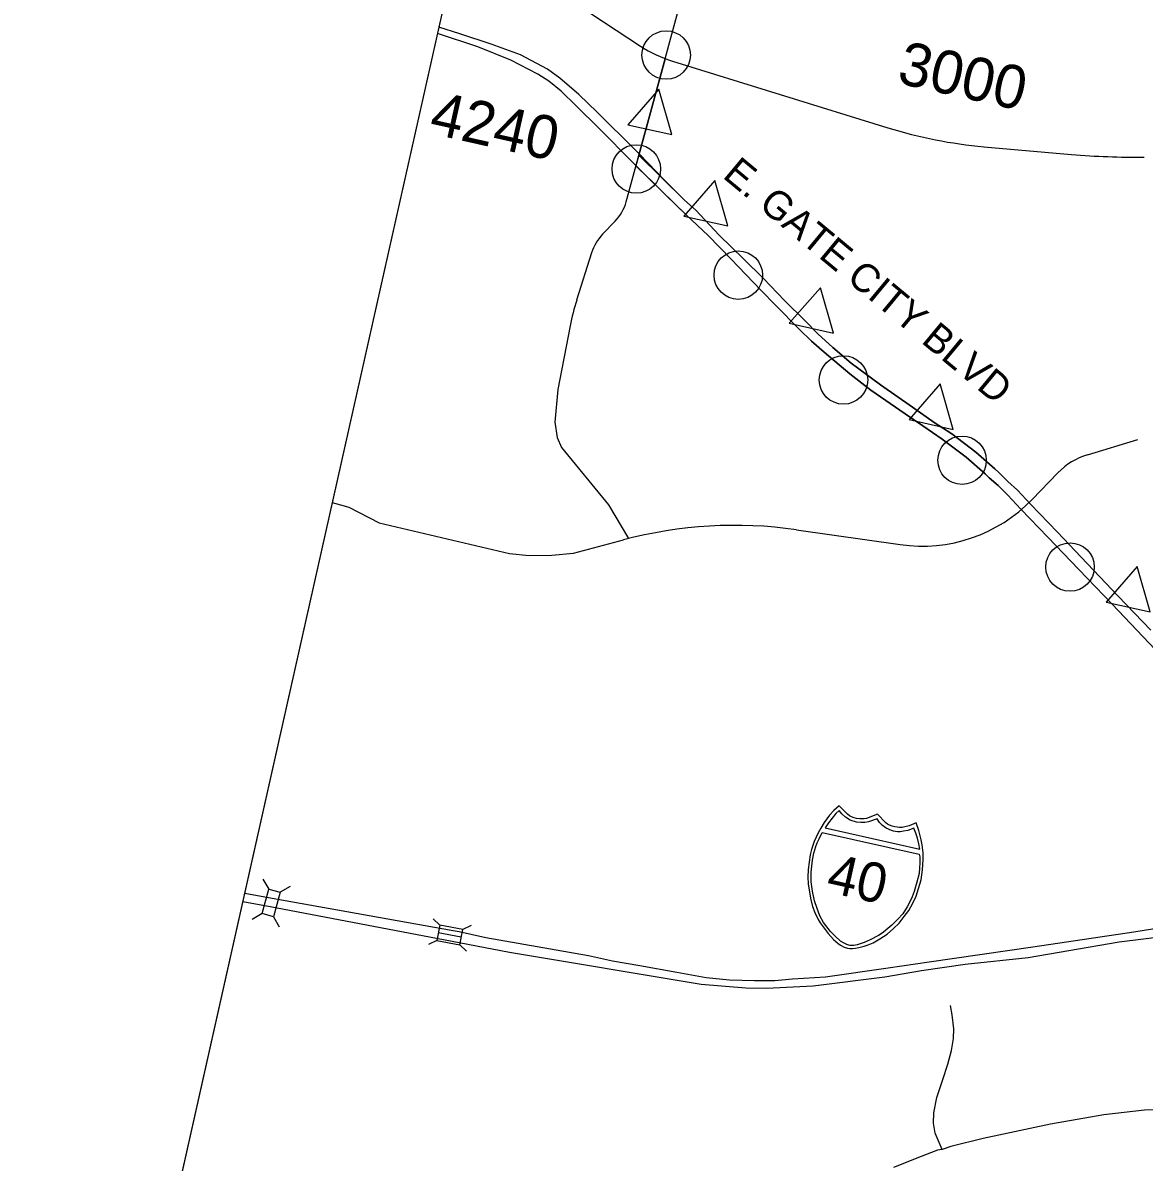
# Model space of a CAD drawing. Extents: x 1784499 to 1786147, y 841097 to 842538.
# Drawn here: x 1784498.9 to 1784672, y 842146.6 to 842322.5 of the extents above; entities that cross this region are included whole.
import ezdxf

# ---------------------------------------------------------------- set-up
doc = ezdxf.new("R2010")
doc.units = 0
for name, color, linetype in [('DEV CONE PLAN VIEW CELL', 7, 'Continuous'), ('Exist Road Non-System Structure Non-Sys NCDOT Attributed CELL', 7, 'Continuous'), ('Exist Road Primary Interstate Divided Center Attributed', 7, 'Continuous'), ('Exist Road Primary Interstate Shield CELL', 7, 'Continuous'), ('Exist Road Primary Interstate Shield Number Label', 7, 'Continuous'), ('Exist Road Primary Interstate Structure Standard Bridge CELL', 7, 'Continuous'), ('Exist Road Secondary Type 51 Attributed', 7, 'Continuous'), ('Exist Road Secondary Type 51 Divided Attributed', 7, 'Continuous'), ('Exist Road Secondary Type 51 Number Label', 7, 'Continuous'), ('Old_Level_1', 7, 'Continuous'), ('Old_Level_40', 7, 'Continuous'), ('Prop DSN Text', 7, 'Continuous'), ('Scratch_Level_3', 7, 'Continuous')]:
    doc.layers.add(name, color=color, linetype=linetype)

msp = doc.modelspace()

# ---------------------------------------------------------------- linework, layer by layer
at = {"layer": 'DEV CONE PLAN VIEW CELL'}
for points in [[(1784597.06, 842312.24), (1784592.26, 842306.76), (1784599.06, 842305.23)], [(1784605.71, 842298.14), (1784600.91, 842292.65), (1784607.71, 842291.13)], [(1784621.99, 842281.6), (1784617.19, 842276.12), (1784623.99, 842274.59)], [(1784640.5, 842266.74), (1784635.7, 842261.26), (1784642.5, 842259.73)], [(1784670.88, 842238.55), (1784666.09, 842233.07), (1784672.89, 842231.54)]]:
    msp.add_lwpolyline(points, close=True, dxfattribs=at)
for centre in [(1784598.19, 842317.51), (1784593.58, 842299.93), (1784609.32, 842283.54), (1784625.55, 842267.36), (1784643.86, 842254.96), (1784660.52, 842238.47)]:
    msp.add_circle(centre, 3.74, dxfattribs=at)
at = {"layer": 'Exist Road Non-System Structure Non-Sys NCDOT Attributed CELL'}
for p, q in [((1784535.95, 842190.3), (1784536.84, 842188.75)), ((1784540.15, 842189.17), (1784538.61, 842188.28)), ((1784535.82, 842184.98), (1784534.31, 842184.08)), ((1784537.58, 842184.5), (1784538.47, 842182.96))]:
    msp.add_line(p, q, dxfattribs=at)
msp.add_lwpolyline([(1784538.61, 842188.28), (1784537.59, 842184.5), (1784535.82, 842184.98), (1784536.84, 842188.75)], close=True, dxfattribs=at)
at = {"layer": 'Exist Road Primary Interstate Divided Center Attributed'}
for p, q in [((1784537.38, 842187.29), (1784533.13, 842188.08)), ((1784565.29, 842182.34), (1784537.38, 842187.29))]:
    msp.add_line(p, q, dxfattribs=at)
for points in [[(1784532.85, 842186.86), (1784537.05, 842186.1), (1784563.83, 842180.98), (1784574.03, 842179.03), (1784603.58, 842174.08), (1784610.49, 842173.51), (1784613.69, 842173.48), (1784620.87, 842173.82), (1784631.94, 842175.24), (1784637.58, 842176.2), (1784644.35, 842177.19), (1784654.07, 842178.21), (1784668.12, 842180.62), (1784691.88, 842183.53)], [(1784695.5, 842186.11), (1784694.75, 842185.99), (1784683.49, 842184.23), (1784670.39, 842182.1), (1784654.76, 842179.82), (1784638.8, 842177.48), (1784632.47, 842176.57), (1784622.77, 842175.18), (1784617.69, 842174.87), (1784614.95, 842174.59), (1784611.84, 842174.62), (1784607.96, 842174.71), (1784604.36, 842175.07), (1784599.81, 842175.9), (1784594.13, 842176.92), (1784589.92, 842177.64), (1784586.2, 842178.48), (1784570.37, 842181.25), (1784566.24, 842182.17), (1784565.29, 842182.34)]]:
    msp.add_lwpolyline(points, dxfattribs=at)
at = {"layer": 'Exist Road Primary Interstate Shield CELL'}
for points in [[(1784626.18, 842179.64), (1784626.51, 842179.59), (1784626.96, 842179.58), (1784627.41, 842179.63), (1784627.94, 842179.73), (1784628.73, 842179.96), (1784629.37, 842180.17), (1784630.13, 842180.46), (1784631.19, 842181.07), (1784632.28, 842181.8), (1784633.3, 842182.67), (1784634.14, 842183.52), (1784634.93, 842184.52), (1784635.62, 842185.46), (1784636.25, 842186.58), (1784636.75, 842187.69), (1784637.14, 842188.87), (1784637.52, 842190.19), (1784637.77, 842191.72), (1784637.86, 842193.32), (1784637.83, 842194.34), (1784637.71, 842195.57), (1784637.57, 842196.37), (1784637.16, 842197.83), (1784636.75, 842198.98), (1784635.68, 842198.53), (1784635, 842198.35), (1784634.6, 842198.27), (1784634.21, 842198.28), (1784633.49, 842198.35), (1784633.06, 842198.47), (1784632.68, 842198.65), (1784632.35, 842198.8), (1784632.1, 842199), (1784630.82, 842200.31), (1784629.1, 842199.67), (1784628.76, 842199.6), (1784628.42, 842199.6), (1784628.09, 842199.59), (1784627.57, 842199.68), (1784627.18, 842199.78), (1784626.8, 842199.94), (1784626.49, 842200.08), (1784626.18, 842200.33), (1784624.87, 842201.64), (1784624.07, 842200.91), (1784623.39, 842200.15), (1784622.59, 842199.05), (1784622.06, 842198.18), (1784621.65, 842197.46), (1784621.05, 842196.1), (1784620.63, 842194.9), (1784620.41, 842194.03), (1784620.08, 842191.81), (1784620.06, 842190.59), (1784620.09, 842189.59), (1784620.44, 842187.38), (1784620.79, 842186.1), (1784621.13, 842185.17), (1784621.66, 842184.08), (1784621.95, 842183.56), (1784623.17, 842181.89), (1784624.03, 842180.97), (1784624.74, 842180.35), (1784625.09, 842180.12), (1784625.65, 842179.82)], [(1784624.89, 842200.9), (1784624.39, 842200.41), (1784623.79, 842199.73), (1784623.26, 842199.01), (1784622.71, 842198.2), (1784637.33, 842194.92), (1784637.16, 842195.75), (1784636.97, 842196.6), (1784636.74, 842197.38), (1784636.43, 842198.16), (1784635.49, 842197.82), (1784634.83, 842197.68), (1784634.32, 842197.62), (1784633.89, 842197.62), (1784633.25, 842197.71), (1784632.97, 842197.79), (1784632.14, 842198.18), (1784631.6, 842198.56), (1784631.11, 842199.06), (1784630.75, 842199.6), (1784629.44, 842199.16), (1784628.87, 842199.05), (1784628.25, 842199.03), (1784627.58, 842199.09), (1784626.61, 842199.42), (1784625.89, 842199.87), (1784625.3, 842200.37)], [(1784637.25, 842194.17), (1784637.32, 842193.73), (1784637.33, 842192.76), (1784637.28, 842192.03), (1784637.22, 842191.19), (1784636.86, 842189.81), (1784636.47, 842188.38), (1784636.15, 842187.56), (1784635.8, 842186.82), (1784635.36, 842186.01), (1784634.71, 842184.95), (1784633.96, 842184.1), (1784633.04, 842183.18), (1784632.1, 842182.4), (1784631.7, 842182.07), (1784630.96, 842181.58), (1784629.67, 842180.95), (1784628.74, 842180.53), (1784627.66, 842180.18), (1784627.13, 842180.07), (1784626.54, 842180.08), (1784626.08, 842180.22), (1784625.55, 842180.49), (1784625.12, 842180.72), (1784624.25, 842181.48), (1784623.56, 842182.2), (1784622.46, 842183.61), (1784621.92, 842184.62), (1784621.47, 842185.77), (1784621.09, 842186.93), (1784620.75, 842188.42), (1784620.59, 842189.87), (1784620.59, 842191.4), (1784620.76, 842193.24), (1784620.98, 842194.33), (1784621.28, 842195.36), (1784621.51, 842195.88), (1784621.79, 842196.53), (1784622.29, 842197.52)]]:
    msp.add_lwpolyline(points, close=True, dxfattribs=at)
at = {"layer": 'Exist Road Primary Interstate Structure Standard Bridge CELL'}
for p, q in [((1784563.23, 842183.17), (1784562.23, 842184.19)), ((1784566.56, 842181.36), (1784563.02, 842182.01)), ((1784568.07, 842183.16), (1784566.78, 842182.54)), ((1784562.8, 842180.83), (1784561.51, 842180.22)), ((1784567.35, 842179.16), (1784566.35, 842180.18))]:
    msp.add_line(p, q, dxfattribs=at)
msp.add_lwpolyline([(1784566.78, 842182.54), (1784563.23, 842183.19), (1784562.8, 842180.83), (1784566.35, 842180.18)], close=True, dxfattribs=at)
at = {"layer": 'Exist Road Secondary Type 51 Attributed'}
for p, q in [((1784592.03, 842294.86), (1784608.26, 842354.55)), ((1784578, 842329.58), (1784594.23, 842318.89)), ((1784599.17, 842316.55), (1784632.42, 842306.26)), ((1784647.24, 842303.36), (1784660.75, 842302.18)), ((1784588.38, 842289.84), (1784590.34, 842291.88)), ((1784586.68, 842286.97), (1784584.36, 842279.69)), ((1784583.35, 842275.72), (1784581.46, 842265.86)), ((1784663.23, 842255.82), (1784671.01, 842258.18)), ((1784582.02, 842256.91), (1784589.29, 842248.07)), ((1784658.65, 842253.02), (1784654.68, 842248.92)), ((1784589.29, 842248.07), (1784592.39, 842242.87)), ((1784618.29, 842244.23), (1784634.32, 842241.94))]:
    msp.add_line(p, q, dxfattribs=at)
for points in [[(1784581.46, 842265.86), (1784580.99, 842260.85), (1784581.37, 842258.45), (1784582.02, 842256.91)], [(1784546.66, 842248.43), (1784549.22, 842247.74), (1784553.87, 842245.32), (1784574, 842240.59), (1784577.05, 842240.26), (1784580.56, 842240.29), (1784583.86, 842240.6), (1784591.58, 842242.66)], [(1784640.81, 842148.57), (1784639.7, 842151.07), (1784639.44, 842152.63), (1784639.52, 842154.21), (1784639.96, 842156.59), (1784640.91, 842159.38), (1784641.68, 842161.75), (1784642.24, 842163.83), (1784642.56, 842165.68), (1784642.61, 842167.17), (1784642.35, 842169.34), (1784642.06, 842170.81)], [(1784753.8, 842155.56), (1784748.67, 842155.57), (1784744.03, 842155.43), (1784738.44, 842155.11), (1784734.44, 842154.67), (1784727.95, 842153.66), (1784725.9, 842153.43), (1784724.28, 842153.35), (1784715.91, 842153.37), (1784708.01, 842153.5), (1784692.53, 842154.16), (1784687.21, 842154.42), (1784680.28, 842154.71), (1784672.03, 842154.64), (1784665.73, 842153.9), (1784657.5, 842152.49), (1784647.14, 842150.27), (1784642.12, 842149.02), (1784640.81, 842148.57)], [(1784640.81, 842148.57), (1784640.05, 842148.48), (1784637.52, 842147.48), (1784633.29, 842145.81)]]:
    msp.add_lwpolyline(points, dxfattribs=at)
for centre, radius, start, end in [((1784604.92, 842335.12), 19.43, 236.6238, 252.8016), ((1784653.41, 842374.08), 70.98, 252.8016, 265.0175), ((1784670.55, 842414.49), 112.74, 265.0175, 270.724), ((1784585.34, 842296.67), 6.92, 316.2178, 344.7891), ((1784593.7, 842284.74), 7.37, 136.2178, 162.3534), ((1784617.45, 842269.17), 34.71, 162.3534, 169.1279), ((1784666.33, 842245.59), 10.69, 106.8881, 135.9796), ((1784637.67, 842265.36), 23.66, 261.8429, 315.9796), ((1784608.8, 842178.01), 66.9, 81.8429, 104.9143)]:
    msp.add_arc(centre, radius, start, end, dxfattribs=at)
at = {"layer": 'Exist Road Secondary Type 51 Divided Attributed'}
for points in [[(1784674.65, 842224.7), (1784667, 842232.72), (1784661.9, 842238.12), (1784657.08, 842243.09), (1784652.92, 842247.39), (1784650.9, 842249.57), (1784649.42, 842251.06), (1784648.04, 842252.27), (1784647.41, 842252.86), (1784644.51, 842255.44), (1784640.78, 842258.23), (1784637.79, 842260.26), (1784635.06, 842262.12), (1784629.79, 842265.8), (1784626.54, 842268.32), (1784622.59, 842271.67), (1784620.63, 842273.34), (1784618.74, 842275.2), (1784615.1, 842278.87), (1784612.78, 842281.23), (1784608.24, 842285.99), (1784604.65, 842289.68), (1784601.3, 842292.8), (1784598.13, 842295.9), (1784592.97, 842300.99), (1784587.91, 842306.14), (1784584.31, 842309.69), (1784581.99, 842311.93), (1784580.08, 842313.49), (1784578.4, 842314.56), (1784574.19, 842316.73), (1784569.12, 842318.78), (1784562.9, 842320.83)], [(1784673, 842228.71), (1784667.96, 842233.99), (1784662.23, 842239.98), (1784658.57, 842243.87), (1784654.43, 842248.16), (1784652.39, 842250.35), (1784650.9, 842251.7), (1784649.53, 842253.06), (1784648.9, 842253.65), (1784646, 842256.23), (1784642.27, 842259.02), (1784639.55, 842260.81), (1784636.21, 842263.14), (1784631.28, 842266.58), (1784626.74, 842269.96), (1784623.92, 842272.38), (1784621.62, 842274.47), (1784619.63, 842276.49), (1784616.46, 842279.6), (1784613.2, 842283.01), (1784610.12, 842286.04), (1784606.39, 842289.73), (1784602.79, 842293.58), (1784601.02, 842295.11), (1784598.02, 842298.07), (1784593.4, 842302.9), (1784587.53, 842308.7), (1784584.7, 842311.43), (1784581.76, 842313.96), (1784579.89, 842315.34), (1784575.68, 842317.52), (1784571.2, 842319.17), (1784566.32, 842320.79), (1784563.12, 842321.83)]]:
    msp.add_lwpolyline(points, dxfattribs=at)
at = {"layer": 'Old_Level_1'}
msp.add_lwpolyline([(1784673, 842228.71), (1784667.96, 842233.99), (1784662.23, 842239.98), (1784658.57, 842243.87), (1784654.43, 842248.16), (1784652.39, 842250.35), (1784650.9, 842251.7), (1784649.53, 842253.06), (1784648.9, 842253.65), (1784646, 842256.23), (1784642.27, 842259.02), (1784639.55, 842260.81), (1784636.21, 842263.14), (1784631.28, 842266.58), (1784626.74, 842269.96), (1784623.92, 842272.38), (1784621.62, 842274.47), (1784619.63, 842276.49), (1784616.46, 842279.6), (1784613.2, 842283.01), (1784610.12, 842286.04), (1784606.39, 842289.73), (1784602.79, 842293.58), (1784601.02, 842295.11), (1784593.98, 842302.04), (1784598.03, 842316.95), (1784593.98, 842302.04), (1784593.53, 842300.39), (1784601.3, 842292.8), (1784604.65, 842289.68), (1784608.24, 842285.99), (1784612.78, 842281.23), (1784615.1, 842278.87), (1784618.74, 842275.2), (1784620.63, 842273.34), (1784622.59, 842271.67), (1784626.54, 842268.32), (1784629.79, 842265.8), (1784635.06, 842262.12), (1784637.79, 842260.26), (1784640.78, 842258.23), (1784644.51, 842255.44), (1784647.41, 842252.86), (1784648.04, 842252.27), (1784649.42, 842251.06), (1784650.9, 842249.57), (1784652.92, 842247.39), (1784657.08, 842243.09), (1784661.9, 842238.12), (1784667, 842232.72), (1784674.65, 842224.7)], dxfattribs=at)
at = {"layer": 'Old_Level_40'}
msp.add_line((1784611.59, 842537.98), (1784498.88, 842035.39), dxfattribs=at)
at = {"layer": 'Scratch_Level_3'}
msp.add_lwpolyline([(1785039.41, 842390.83), (1785050.23, 842439.1), (1784611.48, 842537.49), (1784510.23, 842085.98), (1784998.27, 841976.54), (1785088.7, 842379.78)], close=True, dxfattribs=at)
msp.add_lwpolyline([(1784598.02, 842316.91), (1784594.03, 842302.24), (1784598.02, 842298.07), (1784601.02, 842295.11), (1784602.79, 842293.58), (1784606.39, 842289.73), (1784610.12, 842286.04), (1784613.2, 842283.01), (1784616.46, 842279.6), (1784619.63, 842276.49), (1784621.62, 842274.47), (1784623.92, 842272.38), (1784626.74, 842269.96), (1784631.28, 842266.58), (1784636.21, 842263.14), (1784639.55, 842260.81), (1784642.27, 842259.02), (1784646, 842256.23), (1784648.9, 842253.65), (1784649.53, 842253.06), (1784650.9, 842251.7), (1784652.39, 842250.35), (1784654.43, 842248.16), (1784658.57, 842243.87), (1784662.23, 842239.98), (1784667.96, 842233.99), (1784673, 842228.71)], dxfattribs=at)

# ---------------------------------------------------------------- texts
at = {"layer": 'Exist Road Primary Interstate Shield Number Label'}
msp.add_text('40', height=6.075, rotation=347.3599, dxfattribs=at).set_placement((1784622.69, 842188.38))
at = {"layer": 'Exist Road Secondary Type 51 Number Label'}
for s, p in [('3000', (1784633.62, 842313.24)), ('4240', (1784561.4, 842305.48))]:
    msp.add_text(s, height=6.665, rotation=347.3599, dxfattribs=at).set_placement(p)
at = {"layer": 'Prop DSN Text'}
msp.add_text('E. GATE CITY BLVD', height=4.3971, rotation=320.2701, dxfattribs=at).set_placement((1784606.74, 842298.69))

doc.saveas('drawing.dxf')
